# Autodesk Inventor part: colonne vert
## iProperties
Shininess: 64.0
Length Units: 11269
Angle Units: 11279
Time Units: 11290
Mass Units: 11283
Length Display Precision: 3
Angle Display Precision: 2
Compacted: True
Part Number: colonne vert
Document SubType Name: Modeling
Created: 2005-01
Material: Par défaut
Designer: LEGERET Philippe
Density: 0.0
Volumn: 0.0
Area: 0.0
PropertySet Name: Model Information
Control State: 0
Master: False
Checked Out: False
Author: LEGERET Philippe
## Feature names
1. Extrusion1
2. Chanfrein1 [Chamfer]
3. Chanfrein2 [Chamfer]
4. Perçage1 [Hole]
5. Perçage2 [Hole]
